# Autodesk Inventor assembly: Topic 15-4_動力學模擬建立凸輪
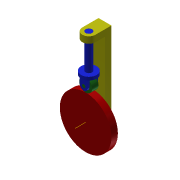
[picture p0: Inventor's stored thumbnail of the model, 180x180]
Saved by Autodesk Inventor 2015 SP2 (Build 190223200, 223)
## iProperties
Created: 2020-03
Part Number: Topic 15-4_動力學模擬建立凸輪
Document SubType Name: Assembly
Designer: Kuan-Lun Hsu
Author: Kuan-Lun Hsu
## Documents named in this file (5)
- C:\Users\Kuan_Lun Hsu\Desktop\Topic 15-4_動力學模擬建立凸輪\Topic 15-4_動力學模擬建立凸輪.iam
- C:\Users\Kuan_Lun Hsu\Desktop\Topic 15-4_動力學模擬建立凸輪\本體.ipt
- C:\Users\Kuan_Lun Hsu\Desktop\Topic 15-4_動力學模擬建立凸輪\從動桿.ipt
- C:\Users\Kuan_Lun Hsu\Desktop\Topic 15-4_動力學模擬建立凸輪\滾輪.ipt
- C:\Users\Kuan_Lun Hsu\Desktop\Topic 15-4_動力學模擬建立凸輪\凸輪.ipt
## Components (4 placed, 4 different names)
1. 本體:1
2. 從動桿:1
3. 滾輪:1
4. 圓盤形凸輪:1
